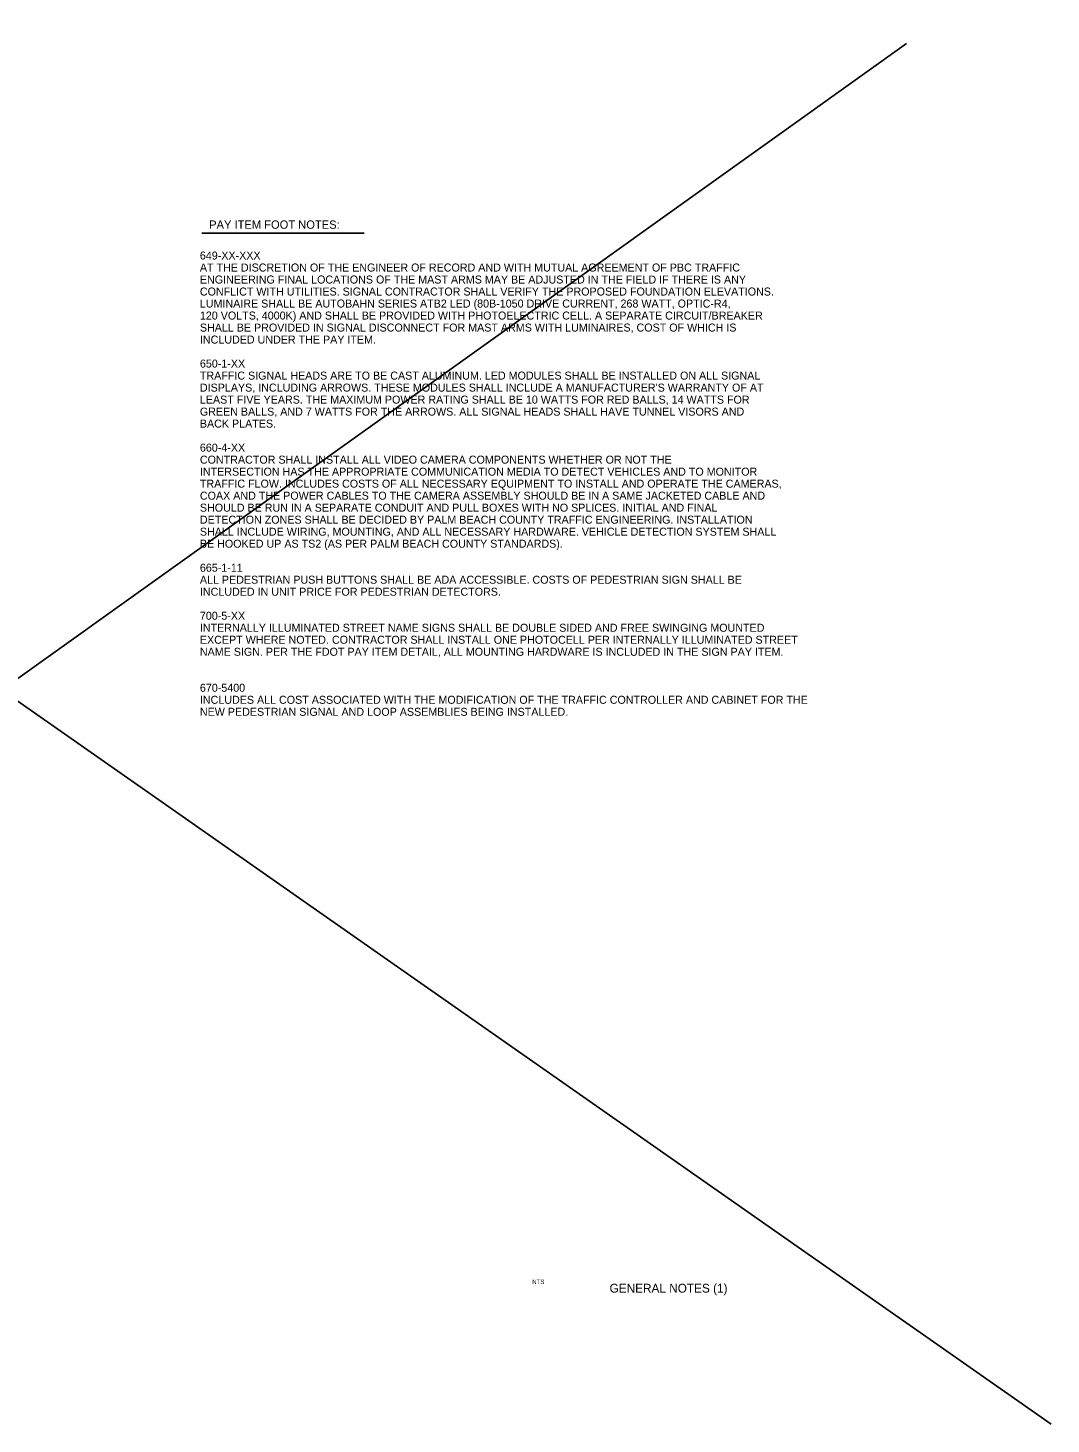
# Model space of a CAD drawing. Extents: x -1.6 to 33.4, y -12.7 to 10.9.
# Drawn here: x 7.37 to 16.32, y -1.35 to 10.86 of the extents above; entities that cross this region are included whole.
import ezdxf

# ---------------------------------------------------------------- set-up
doc = ezdxf.new("R2010")
doc.units = 0
doc.layers.add('NonPlottingEle_dp', color=7, linetype='Continuous')

msp = doc.modelspace()

# ---------------------------------------------------------------- linework, layer by layer
at = {"layer": 'NonPlottingEle_dp'}
for p, q in [((-1.131, 10.856), (16.32, -1.353)), ((15.056, 10.719), (-1.571, -1.16)), ((8.896, 9.062), (10.313, 9.062))]:
    msp.add_line(p, q, dxfattribs=at)

# ---------------------------------------------------------------- texts
for s, height, p in [('PAY ITEM FOOT NOTES:', 0.07279, (8.959, 9.1)), ('AT THE DISCRETION OF THE ENGINEER OF RECORD AND WITH MUTUAL AGREEMENT OF PBC TRAFFIC', 0.07, (8.878, 8.726)), ('649-XX-XXX', 0.07, (8.878, 8.831)), ('ENGINEERING FINAL LOCATIONS OF THE MAST ARMS MAY BE ADJUSTED IN THE FIELD IF THERE IS ANY', 0.07, (8.878, 8.621)), ('CONFLICT WITH UTILITIES. SIGNAL CONTRACTOR SHALL VERIFY THE PROPOSED FOUNDATION ELEVATIONS.', 0.07, (8.878, 8.516)), ('LUMINAIRE SHALL BE AUTOBAHN SERIES ATB2 LED (80B-1050 DRIVE CURRENT, 268 WATT, OPTIC-R4, ', 0.07, (8.878, 8.411)), ('120 VOLTS, 4000K) AND SHALL BE PROVIDED WITH PHOTOELECTRIC CELL. A SEPARATE CIRCUIT/BREAKER', 0.07, (8.878, 8.306)), ('SHALL BE PROVIDED IN SIGNAL DISCONNECT FOR MAST ARMS WITH LUMINAIRES, COST OF WHICH IS ', 0.07, (8.878, 8.201)), ('INCLUDED UNDER THE PAY ITEM.', 0.07, (8.878, 8.096)), ('650-1-XX', 0.07, (8.878, 7.886)), ('TRAFFIC SIGNAL HEADS ARE TO BE CAST ALUMINUM. LED MODULES SHALL BE INSTALLED ON ALL SIGNAL', 0.07, (8.878, 7.781)), ("DISPLAYS, INCLUDING ARROWS. THESE MODULES SHALL INCLUDE A MANUFACTURER'S WARRANTY OF AT ", 0.07, (8.878, 7.676)), ('LEAST FIVE YEARS. THE MAXIMUM POWER RATING SHALL BE 10 WATTS FOR RED BALLS, 14 WATTS FOR', 0.07, (8.878, 7.571)), ('GREEN BALLS, AND 7 WATTS FOR THE ARROWS. ALL SIGNAL HEADS SHALL HAVE TUNNEL VISORS AND ', 0.07, (8.878, 7.466)), ('BACK PLATES.', 0.07, (8.878, 7.361)), ('660-4-XX', 0.07, (8.878, 7.151)), ('CONTRACTOR SHALL INSTALL ALL VIDEO CAMERA COMPONENTS WHETHER OR NOT THE ', 0.07, (8.878, 7.046)), ('INTERSECTION HAS THE APPROPRIATE COMMUNICATION MEDIA TO DETECT VEHICLES AND TO MONITOR', 0.07, (8.878, 6.941)), ('TRAFFIC FLOW. INCLUDES COSTS OF ALL NECESSARY EQUIPMENT TO INSTALL AND OPERATE THE CAMERAS,', 0.07, (8.878, 6.836)), ('COAX AND THE POWER CABLES TO THE CAMERA ASSEMBLY SHOULD BE IN A SAME JACKETED CABLE AND', 0.07, (8.878, 6.731)), ('SHOULD BE RUN IN A SEPARATE CONDUIT AND PULL BOXES WITH NO SPLICES. INITIAL AND FINAL ', 0.07, (8.878, 6.626)), ('SHALL INCLUDE WIRING, MOUNTING, AND ALL NECESSARY HARDWARE. VEHICLE DETECTION SYSTEM SHALL', 0.07, (8.878, 6.416)), ('DETECTION ZONES SHALL BE DECIDED BY PALM BEACH COUNTY TRAFFIC ENGINEERING. INSTALLATION ', 0.07, (8.878, 6.521)), ('BE HOOKED UP AS TS2 (AS PER PALM BEACH COUNTY STANDARDS).', 0.07, (8.878, 6.311)), ('665-1-11', 0.07, (8.878, 6.101)), ('ALL PEDESTRIAN PUSH BUTTONS SHALL BE ADA ACCESSIBLE. COSTS OF PEDESTRIAN SIGN SHALL BE', 0.07, (8.878, 5.996)), ('INCLUDED IN UNIT PRICE FOR PEDESTRIAN DETECTORS.', 0.07, (8.878, 5.891)), ('700-5-XX', 0.07, (8.878, 5.681)), ('INTERNALLY ILLUMINATED STREET NAME SIGNS SHALL BE DOUBLE SIDED AND FREE SWINGING MOUNTED ', 0.07, (8.878, 5.576)), ('EXCEPT WHERE NOTED. CONTRACTOR SHALL INSTALL ONE PHOTOCELL PER INTERNALLY ILLUMINATED STREET', 0.07, (8.878, 5.471)), ('NAME SIGN. PER THE FDOT PAY ITEM DETAIL, ALL MOUNTING HARDWARE IS INCLUDED IN THE SIGN PAY ITEM.', 0.07, (8.878, 5.366)), ('670-5400', 0.07, (8.878, 5.051)), ('INCLUDES ALL COST ASSOCIATED WITH THE MODIFICATION OF THE TRAFFIC CONTROLLER AND CABINET FOR THE', 0.07, (8.878, 4.946)), ('NEW PEDESTRIAN SIGNAL AND LOOP ASSEMBLIES BEING INSTALLED.', 0.07, (8.878, 4.841)), ('NTS', 0.0385, (11.784, -0.128)), ('   GENERAL NOTES (1)    ', 0.07709, (12.374, -0.203))]:
    msp.add_text(s, height=height, dxfattribs=at).set_placement(p)

doc.saveas('drawing.dxf')
